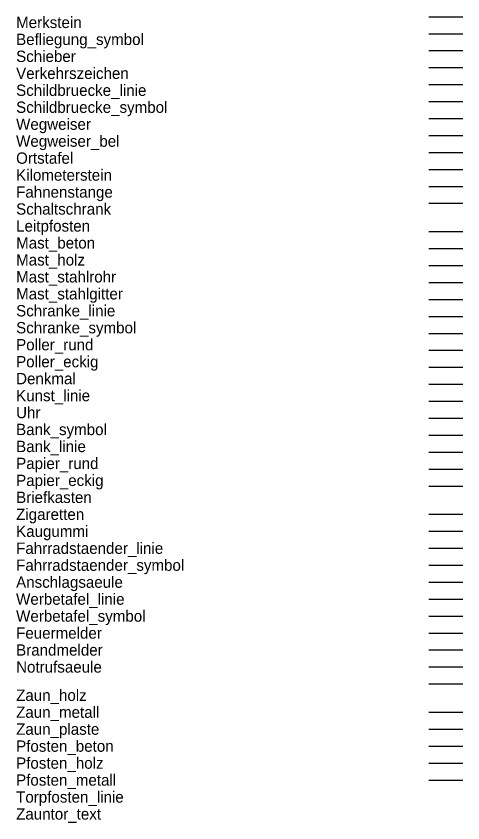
# Model space of a CAD drawing. Extents: x 0 to 177, y -135 to 1.
# Drawn here: x 43.5 to 83, y -135.3 to -63.9 of the extents above; entities that cross this region are included whole.
import ezdxf

# ---------------------------------------------------------------- set-up
doc = ezdxf.new("R2010")
doc.units = 0
for name, color, linetype in [('Anschlagsaeule', 7, 'Continuous'), ('Aufrichter_gas', 7, 'Continuous'), ('Bank_linie', 7, 'Continuous'), ('Bank_symbol', 7, 'Continuous'), ('Befliegung_symbol', 7, 'Continuous'), ('Beobrohr_gas', 7, 'Continuous'), ('Brandmelder', 7, 'Continuous'), ('Briefkasten', 7, 'Continuous'), ('Denkmal', 7, 'Continuous'), ('Doppelschacht_tel', 7, 'Continuous'), ('Elektrant', 7, 'Continuous'), ('Elektromotor', 7, 'Continuous'), ('Elektropfeil', 7, 'Continuous'), ('Fahnenstange', 7, 'Continuous'), ('Fahrradstaender_linie', 7, 'Continuous'), ('Fahrradstaender_symbol', 7, 'Continuous'), ('Fernsprechhaus', 7, 'Continuous'), ('Feuermelder', 7, 'Continuous'), ('Freileitung', 7, 'Continuous'), ('Hochspannungsmast', 7, 'Continuous'), ('Kabel_daten', 7, 'Continuous'), ('Kabel_tel', 7, 'Continuous'), ('Kaugummi', 7, 'Continuous'), ('Kilometerstein', 7, 'Continuous'), ('Kunst_linie', 7, 'Continuous'), ('Ladestation', 7, 'Continuous'), ('Leitpfosten', 7, 'Continuous'), ('Mast_beton', 7, 'Continuous'), ('Mast_holz', 7, 'Continuous'), ('Mast_stahlgitter', 7, 'Continuous'), ('Mast_stahlrohr', 7, 'Continuous'), ('Merkstein', 7, 'Continuous'), ('Merkstein_elektro', 7, 'Continuous'), ('Merkstein_gas', 7, 'Continuous'), ('Merkstein_post', 7, 'Continuous'), ('Notrufsaeule', 7, 'Continuous'), ('Ortstafel', 7, 'Continuous'), ('Papier_eckig', 7, 'Continuous'), ('Papier_rund', 7, 'Continuous'), ('Pfosten_beton', 7, 'Continuous'), ('Pfosten_holz', 7, 'Continuous'), ('Pfosten_metall', 7, 'Continuous'), ('Poller_eckig', 7, 'Continuous'), ('Poller_rund', 7, 'Continuous'), ('Regelstation_gas', 7, 'Continuous'), ('Rohr_gas', 7, 'Continuous'), ('Schacht_tel', 7, 'Continuous'), ('Schaltschrank', 7, 'Continuous'), ('Schaltschrank_elektro', 7, 'Continuous'), ('Schaltschrank_tel', 7, 'Continuous'), ('Schaltschrank_tv', 7, 'Continuous'), ('Schieber', 7, 'Continuous'), ('Schieber_gas', 7, 'Continuous'), ('Schildbruecke_linie', 7, 'Continuous'), ('Schildbruecke_symbol', 7, 'Continuous'), ('Schrank_post', 7, 'Continuous'), ('Schranke_linie', 7, 'Continuous'), ('Schranke_symbol', 7, 'Continuous'), ('Schrift_fh', 7, 'Continuous'), ('Schrift_g', 7, 'Continuous'), ('Schrift_post', 7, 'Continuous'), ('Schrift_tel', 7, 'Continuous'), ('Schrift_tv', 7, 'Continuous'), ('Schutzrohr_daten', 7, 'Continuous'), ('Schutzrohr_gas', 7, 'Continuous'), ('Schutzrohr_tel', 7, 'Continuous'), ('Solar', 7, 'Continuous'), ('Sonstiges_daten', 7, 'Continuous'), ('Sonstiges_elektro', 7, 'Continuous'), ('Sonstiges_gas', 7, 'Continuous'), ('Sonstiges_telekom', 7, 'Continuous'), ('Text_kabel_daten', 7, 'Continuous'), ('Text_kabel_tel', 7, 'Continuous'), ('Text_rohr_gas', 7, 'Continuous'), ('Text_schutzrohr_daten', 7, 'Continuous'), ('Text_schutzrohr_gas', 7, 'Continuous'), ('Text_schutzrohr_tel', 7, 'Continuous'), ('Torpfosten_linie', 7, 'Continuous'), ('Trafo', 7, 'Continuous'), ('Uhr', 7, 'Continuous'), ('Verkehrszeichen', 7, 'Continuous'), ('Wegweiser', 7, 'Continuous'), ('Wegweiser_bel', 7, 'Continuous'), ('Werbetafel_linie', 7, 'Continuous'), ('Werbetafel_symbol', 7, 'Continuous'), ('Windrad', 7, 'Continuous'), ('Zaun_holz', 7, 'Continuous'), ('Zaun_metall', 7, 'Continuous'), ('Zaun_plaste', 7, 'Continuous'), ('Zauntor_text', 7, 'Continuous'), ('Zigaretten', 7, 'Continuous')]:
    doc.layers.add(name, color=color, linetype=linetype)

msp = doc.modelspace()

# ---------------------------------------------------------------- linework, layer by layer
at = {"layer": 'Aufrichter_gas'}
msp.add_line((80, -120), (83, -120), dxfattribs=at)
at = {"layer": 'Beobrohr_gas'}
msp.add_line((80, -118.5), (83, -118.5), dxfattribs=at)
at = {"layer": 'Doppelschacht_tel'}
msp.add_line((80, -98), (83, -98), dxfattribs=at)
at = {"layer": 'Elektrant'}
msp.add_line((80, -71.5), (83, -71.5), dxfattribs=at)
at = {"layer": 'Elektromotor'}
msp.add_line((80, -68.5), (83, -68.5), dxfattribs=at)
at = {"layer": 'Elektropfeil'}
msp.add_line((80, -65.5), (83, -65.5), dxfattribs=at)
at = {"layer": 'Fernsprechhaus'}
msp.add_line((80, -99.5), (83, -99.5), dxfattribs=at)
at = {"layer": 'Freileitung'}
msp.add_line((80, -74.5), (83, -74.5), dxfattribs=at)
at = {"layer": 'Hochspannungsmast'}
msp.add_line((80, -73), (83, -73), dxfattribs=at)
at = {"layer": 'Kabel_daten'}
msp.add_line((80, -125.5), (83, -125.5), dxfattribs=at)
at = {"layer": 'Kabel_tel'}
msp.add_line((80, -83), (83, -83), dxfattribs=at)
at = {"layer": 'Ladestation'}
msp.add_line((80, -77.5), (83, -77.5), dxfattribs=at)
at = {"layer": 'Merkstein_elektro'}
msp.add_line((80, -64), (83, -64), dxfattribs=at)
at = {"layer": 'Merkstein_gas'}
msp.add_line((80, -114), (83, -114), dxfattribs=at)
at = {"layer": 'Merkstein_post'}
msp.add_line((80, -89), (83, -89), dxfattribs=at)
at = {"layer": 'Regelstation_gas'}
msp.add_line((80, -121.5), (83, -121.5), dxfattribs=at)
at = {"layer": 'Rohr_gas'}
msp.add_line((80, -108), (83, -108), dxfattribs=at)
at = {"layer": 'Schacht_tel'}
msp.add_line((80, -96.5), (83, -96.5), dxfattribs=at)
at = {"layer": 'Schaltschrank_elektro'}
msp.add_line((80, -67), (83, -67), dxfattribs=at)
at = {"layer": 'Schaltschrank_tel'}
msp.add_line((80, -92), (83, -92), dxfattribs=at)
at = {"layer": 'Schaltschrank_tv'}
msp.add_line((80, -102.5), (83, -102.5), dxfattribs=at)
at = {"layer": 'Schieber_gas'}
msp.add_line((80, -117), (83, -117), dxfattribs=at)
at = {"layer": 'Schrank_post'}
msp.add_line((80, -95), (83, -95), dxfattribs=at)
at = {"layer": 'Schrift_fh'}
msp.add_line((80, -101), (83, -101), dxfattribs=at)
at = {"layer": 'Schrift_g'}
msp.add_line((80, -115.5), (83, -115.5), dxfattribs=at)
at = {"layer": 'Schrift_post'}
msp.add_line((80, -90.5), (83, -90.5), dxfattribs=at)
at = {"layer": 'Schrift_tel'}
msp.add_line((80, -93.5), (83, -93.5), dxfattribs=at)
at = {"layer": 'Schrift_tv'}
msp.add_line((80, -104), (83, -104), dxfattribs=at)
at = {"layer": 'Schutzrohr_daten'}
msp.add_line((80, -128.5), (83, -128.5), dxfattribs=at)
at = {"layer": 'Schutzrohr_gas'}
msp.add_line((80, -111), (83, -111), dxfattribs=at)
at = {"layer": 'Schutzrohr_tel'}
msp.add_line((80, -86), (83, -86), dxfattribs=at)
at = {"layer": 'Solar'}
msp.add_line((80, -80.5), (83, -80.5), dxfattribs=at)
at = {"layer": 'Sonstiges_daten'}
msp.add_line((80, -131.5), (83, -131.5), dxfattribs=at)
at = {"layer": 'Sonstiges_elektro'}
msp.add_line((80, -76), (83, -76), dxfattribs=at)
at = {"layer": 'Sonstiges_gas'}
msp.add_line((80, -123), (83, -123), dxfattribs=at)
at = {"layer": 'Sonstiges_telekom'}
msp.add_line((80, -105.5), (83, -105.5), dxfattribs=at)
at = {"layer": 'Text_kabel_daten'}
msp.add_line((80, -127), (83, -127), dxfattribs=at)
at = {"layer": 'Text_kabel_tel'}
msp.add_line((80, -84.5), (83, -84.5), dxfattribs=at)
at = {"layer": 'Text_rohr_gas'}
msp.add_line((80, -109.5), (83, -109.5), dxfattribs=at)
at = {"layer": 'Text_schutzrohr_daten'}
msp.add_line((80, -130), (83, -130), dxfattribs=at)
at = {"layer": 'Text_schutzrohr_gas'}
msp.add_line((80, -112.5), (83, -112.5), dxfattribs=at)
at = {"layer": 'Text_schutzrohr_tel'}
msp.add_line((80, -87.5), (83, -87.5), dxfattribs=at)
at = {"layer": 'Trafo'}
msp.add_line((80, -70), (83, -70), dxfattribs=at)
at = {"layer": 'Windrad'}
msp.add_line((80, -79), (83, -79), dxfattribs=at)

# ---------------------------------------------------------------- texts
at = {"layer": 'Anschlagsaeule'}
msp.add_text('Anschlagsaeule', height=1, dxfattribs=at).set_placement((43.5, -114.5))
at = {"layer": 'Bank_linie'}
msp.add_text('Bank_linie', height=1, dxfattribs=at).set_placement((43.5, -102.5))
at = {"layer": 'Bank_symbol'}
msp.add_text('Bank_symbol', height=1, dxfattribs=at).set_placement((43.5, -101))
at = {"layer": 'Befliegung_symbol'}
msp.add_text('Befliegung_symbol', height=1, dxfattribs=at).set_placement((43.5, -66.5))
at = {"layer": 'Brandmelder'}
msp.add_text('Brandmelder', height=1, dxfattribs=at).set_placement((43.5, -120.5))
at = {"layer": 'Briefkasten'}
msp.add_text('Briefkasten', height=1, dxfattribs=at).set_placement((43.5, -107))
at = {"layer": 'Denkmal'}
msp.add_text('Denkmal', height=1, dxfattribs=at).set_placement((43.5, -96.5))
at = {"layer": 'Fahnenstange'}
msp.add_text('Fahnenstange', height=1, dxfattribs=at).set_placement((43.5, -80))
at = {"layer": 'Fahrradstaender_linie'}
msp.add_text('Fahrradstaender_linie', height=1, dxfattribs=at).set_placement((43.5, -111.5))
at = {"layer": 'Fahrradstaender_symbol'}
msp.add_text('Fahrradstaender_symbol', height=1, dxfattribs=at).set_placement((43.5, -113))
at = {"layer": 'Feuermelder'}
msp.add_text('Feuermelder', height=1, dxfattribs=at).set_placement((43.5, -119))
at = {"layer": 'Kaugummi'}
msp.add_text('Kaugummi', height=1, dxfattribs=at).set_placement((43.5, -110))
at = {"layer": 'Kilometerstein'}
msp.add_text('Kilometerstein', height=1, dxfattribs=at).set_placement((43.5, -78.5))
at = {"layer": 'Kunst_linie'}
msp.add_text('Kunst_linie', height=1, dxfattribs=at).set_placement((43.5, -98))
at = {"layer": 'Leitpfosten'}
msp.add_text('Leitpfosten', height=1, dxfattribs=at).set_placement((43.5, -83))
at = {"layer": 'Mast_beton'}
msp.add_text('Mast_beton', height=1, dxfattribs=at).set_placement((43.5, -84.5))
at = {"layer": 'Mast_holz'}
msp.add_text('Mast_holz', height=1, dxfattribs=at).set_placement((43.5, -86))
at = {"layer": 'Mast_stahlgitter'}
msp.add_text('Mast_stahlgitter', height=1, dxfattribs=at).set_placement((43.5, -89))
at = {"layer": 'Mast_stahlrohr'}
msp.add_text('Mast_stahlrohr', height=1, dxfattribs=at).set_placement((43.5, -87.5))
at = {"layer": 'Merkstein'}
msp.add_text('Merkstein', height=1, dxfattribs=at).set_placement((43.5, -65))
at = {"layer": 'Notrufsaeule'}
msp.add_text('Notrufsaeule', height=1, dxfattribs=at).set_placement((43.5, -122))
at = {"layer": 'Ortstafel'}
msp.add_text('Ortstafel', height=1, dxfattribs=at).set_placement((43.5, -77))
at = {"layer": 'Papier_eckig'}
msp.add_text('Papier_eckig', height=1, dxfattribs=at).set_placement((43.5, -105.5))
at = {"layer": 'Papier_rund'}
msp.add_text('Papier_rund', height=1, dxfattribs=at).set_placement((43.5, -104))
at = {"layer": 'Pfosten_beton'}
msp.add_text('Pfosten_beton', height=1, dxfattribs=at).set_placement((43.5, -129))
at = {"layer": 'Pfosten_holz'}
msp.add_text('Pfosten_holz', height=1, dxfattribs=at).set_placement((43.5, -130.5))
at = {"layer": 'Pfosten_metall'}
msp.add_text('Pfosten_metall', height=1, dxfattribs=at).set_placement((43.5, -132))
at = {"layer": 'Poller_eckig'}
msp.add_text('Poller_eckig', height=1, dxfattribs=at).set_placement((43.5, -95))
at = {"layer": 'Poller_rund'}
msp.add_text('Poller_rund', height=1, dxfattribs=at).set_placement((43.5, -93.5))
at = {"layer": 'Schaltschrank'}
msp.add_text('Schaltschrank', height=1, dxfattribs=at).set_placement((43.5, -81.5))
at = {"layer": 'Schieber'}
msp.add_text('Schieber', height=1, dxfattribs=at).set_placement((43.5, -68))
at = {"layer": 'Schildbruecke_linie'}
msp.add_text('Schildbruecke_linie', height=1, dxfattribs=at).set_placement((43.5, -71))
at = {"layer": 'Schildbruecke_symbol'}
msp.add_text('Schildbruecke_symbol', height=1, dxfattribs=at).set_placement((43.5, -72.5))
at = {"layer": 'Schranke_linie'}
msp.add_text('Schranke_linie', height=1, dxfattribs=at).set_placement((43.5, -90.5))
at = {"layer": 'Schranke_symbol'}
msp.add_text('Schranke_symbol', height=1, dxfattribs=at).set_placement((43.5, -92))
at = {"layer": 'Torpfosten_linie'}
msp.add_text('Torpfosten_linie', height=1, dxfattribs=at).set_placement((43.5, -133.5))
at = {"layer": 'Uhr'}
msp.add_text('Uhr', height=1, dxfattribs=at).set_placement((43.5, -99.5))
at = {"layer": 'Verkehrszeichen'}
msp.add_text('Verkehrszeichen', height=1, dxfattribs=at).set_placement((43.5, -69.5))
at = {"layer": 'Wegweiser'}
msp.add_text('Wegweiser', height=1, dxfattribs=at).set_placement((43.5, -74))
at = {"layer": 'Wegweiser_bel'}
msp.add_text('Wegweiser_bel', height=1, dxfattribs=at).set_placement((43.5, -75.5))
at = {"layer": 'Werbetafel_linie'}
msp.add_text('Werbetafel_linie', height=1, dxfattribs=at).set_placement((43.5, -116))
at = {"layer": 'Werbetafel_symbol'}
msp.add_text('Werbetafel_symbol', height=1, dxfattribs=at).set_placement((43.5, -117.5))
at = {"layer": 'Zaun_holz'}
msp.add_text('Zaun_holz', height=1, dxfattribs=at).set_placement((43.5, -124.5))
at = {"layer": 'Zaun_metall'}
msp.add_text('Zaun_metall', height=1, dxfattribs=at).set_placement((43.5, -126))
at = {"layer": 'Zaun_plaste'}
msp.add_text('Zaun_plaste', height=1, dxfattribs=at).set_placement((43.5, -127.5))
at = {"layer": 'Zauntor_text'}
msp.add_text('Zauntor_text', height=1, dxfattribs=at).set_placement((43.5, -135))
at = {"layer": 'Zigaretten'}
msp.add_text('Zigaretten', height=1, dxfattribs=at).set_placement((43.5, -108.5))

doc.saveas('drawing.dxf')
